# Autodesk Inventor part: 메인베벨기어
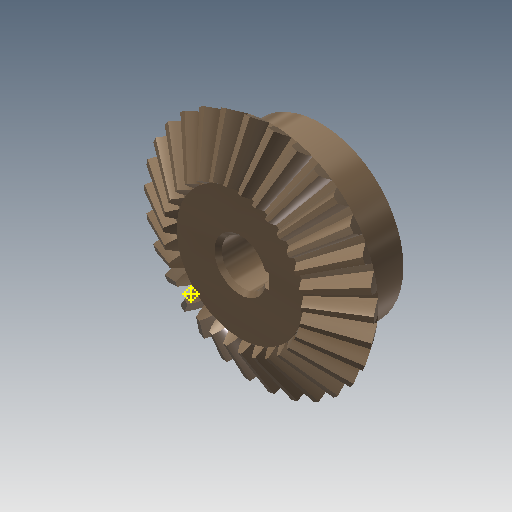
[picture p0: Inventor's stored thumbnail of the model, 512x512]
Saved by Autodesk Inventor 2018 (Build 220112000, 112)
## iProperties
Created: 2018-09
Part Number: 메인베벨기어
Material: 강철, 탄소
Document SubType Name: Modeling
Categories: <?xml version="1.0" encoding="UTF-16"?> <MemberInstance><Categories><FamilyTemplate><FamilyTemplateParameter ValueType="xs:double" Id="1" ObjectReferenceKey="da
Mass: 290.333 g
Surface Area: 107.709 cm^2
Volume: 36.8911 cm^3
Density: 7.87 g/cm^3
Appearance: 얼룩무늬
CustomPartVersion: 1
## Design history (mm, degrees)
node "맨 위 점"
node "메쉬 평면2"
sketch "톱니 본체 스케치"
  geometry: L1 (0, 0)-(28.669, -21.997); L2 (28.669, -21.997)-(31.109, -18.336); L3 (31.109, -18.336)-(0, 0); L4 (30, -20)-(0, 0); L5 (17.219, -13.212)-(18.685, -11.013); L6 (28.669, -21.997)-(17.219, -13.212); L7 (31.109, -18.336)-(18.685, -11.013); L8 (0, -39.387)-(0, 6.564) reference; L9 (0, -20)-(31.109, -20)
  constraints: 16 end point, 4 point on line, 3 perpendicular, 2 collinear, 1 horizontal alignment, 1 vertical alignment
  dimensions: "d0" = 60 diameter of L4.start L8 (= da_de); "d1" = 57.33744 diameter of L1.end L8 (= da_dfe); "d2" = 62.2188 diameter of L2.end L8 (= da_dae); "d3" = 14.4 distance between parallel lines of L2 L5 (= da_b); "d4" = 18.3359 vertical distance of L2.end L1.start (= da_ve)
revolve "톱니 본체" sketch "톱니 본체 스케치" stored, may be unused: angle "d5" = 90 deg
node "시작점"
node "톱니 평면"
sketch "시작 스케치"
  geometry: L1 (0, -23.505)-(0, 10.645) reference; L2 (-0.709, -2.928)-(0.709, -2.928); A1 r 19.188 centre (-19.457, -7.014) between (-0.709, -2.928) and (-3.232, 3.229); A2 r 19.188 centre (19.457, -7.014) between (3.232, 3.229) and (0.709, -2.928); A3 r 57.403 centre (0, -54.083) between (3.232, 3.229) and (-3.232, 3.229); 1 further point
  constraints: 6 point on circle, 3 centre point, 3 symmetric about line, 2 end point, 1 coincident, 1 perpendicular, 1 other
  dimensions: "d7" = 19.18795 radius of A1 (= fd_rr); "d8" = 19.45712 horizontal distance of point (0, -54.083) A1.centre (= fd_x); "d9" = 47.06905 vertical distance of point (0, -54.083) A1.centre (= fd_y); "d57" = 57.40327 radius of A3 (= 0.5 x fd_dva + 0.3 x da_he); "d58" = 51.15527 distance from line of A3.centre L2 (= 0.5 x fd_dva - 1.12 x da_he)
node "끝점"
  node "끝 평면"
sketch "3D 스케치 오른쪽"
  node "Helical Curve Right" dims "d65" = 229.90621 (computed from da_dm, da_delta, da_beta), "d66" = 31.5, "d67" = 60 (= da_de), "d68" = -9.82794 (= -da_delta), "d69" = 8.10972 (computed from fd_loft, da_delta)
node "끝 평면 오른쪽"
sketch "끝 스케치 오른쪽"
  geometry: L1 (0, -41.54)-(0, 13.178) reference; L2 (-0.422, -1.69)-(0.422, -1.69); A1 r 11.427 centre (-11.587, -4.123) between (-0.422, -1.69) and (-1.925, 1.977); A2 r 11.427 centre (11.587, -4.123) between (1.925, 1.977) and (0.422, -1.69); A3 r 34.184 centre (0, -32.153) between (1.925, 1.977) and (-1.925, 1.977); 1 further point
  constraints: 6 point on circle, 3 centre point, 3 symmetric about line, 2 end point, 1 coincident, 1 perpendicular, 1 other
  dimensions: "d70" = 11.58699 horizontal distance of A3.centre A1.centre (computed from fd_x, fd_ratio); "d71" = 28.03028 vertical distance of point (0, -32.153) A1.centre (computed from fd_y, fd_ratio); "d72" = 11.4267 radius of A1 (computed from fd_rr, fd_ratio); "d73" = 30.46369 distance from line of point (0, -32.153) L2 (computed from d58, fd_ratio); "d74" = 34.18446 radius of A3 (computed from d57, fd_ratio)
feature "로프트 오른쪽" sketch "끝 스케치 오른쪽" dims "d75" = 0, "d77" = 0, "d79" = 0, "d80" = 90 deg, "d85" = 20, "d92" = 90 deg, "d93" = 90 deg, "da_teethtype" = 0 [user parameter]
sketch "3D 스케치 왼쪽"
  node "Helical Curve Left" dims "d26" = 229.90621 (computed from da_dm, da_delta, da_beta), "d27" = 8.10972 (computed from fd_loft, da_delta), "d28" = 60 (= da_de), "d29" = -9.82794 (= -da_delta)
node "끝 평면 왼쪽"
sketch "끝 스케치 왼쪽" dims "d56" = 10.3728 (derived)
  geometry: L1 (0, -43.753)-(0, 15.405) reference; L2 (-0.422, -1.678)-(0.422, -1.678); A1 r 11.427 centre (-11.587, -4.111) between (-0.422, -1.678) and (-1.925, 1.988); A2 r 11.427 centre (11.587, -4.111) between (1.925, 1.988) and (0.422, -1.678); A3 r 34.184 centre (0, -32.142) between (1.925, 1.988) and (-1.925, 1.988); 2 further points; 1 other entity
  constraints: 6 point on circle, 3 centre point, 3 symmetric about line, 2 end point, 1 coincident, 2 other
  dimensions: "d30" = 11.4267 radius of A1 (computed from fd_rr, fd_ratio); "d31" = 11.58699 horizontal distance of point (0, -32.142) A1.centre (computed from fd_x, fd_ratio); "d32" = 28.03028 vertical distance of A1.centre point (0, -32.142) (computed from fd_y, fd_ratio); "d61" = 34.18446 radius of A3 (computed from d57, fd_ratio); "d62" = 30.46369 distance from line of point (0, -32.142) L2 (computed from d58, fd_ratio)
feature "로프트 왼쪽" sketch "끝 스케치 왼쪽" dims "d35" = 0, "d37" = 0, "d39" = 0, "d40" = 90 deg, "d84" = 10, "d90" = 90 deg, "d91" = 90 deg, "da_teethtype" = 0 [user parameter]
sketch "본체 스케치"
  geometry: L1 (0, -35.038)-(0, -19.531) reference; L2 (28.669, -21.997)-(17.219, -13.212) reference; L3 (17.219, -13.212)-(0, -13.212); L4 (28.669, -21.997)-(0, -21.997)
  constraints: 4 end point, 2 perpendicular, 2 point on line
revolve "본체 고정" sketch "본체 스케치" stored, may be unused: angle "d46" = 90 deg
feature "피치 지름" dims angle "d47" = 90 deg
sketch "스케치8"
  geometry: C1 r 22.5 at (0, 0); 1 further point
  constraints: 1 centre point, 1 coincident
  dimensions: "d94" = 45 diameter of C1
extrude "돌출1" join sketch "스케치8" distance "d95" = 13; taper "d96" = 0 deg
sketch "스케치9"
  geometry: 1 further point
hole "구멍1" sketch "스케치9" at (0, 0) diameter "d97" = 12; stored, may be unused: countersink angle "d101" = 90 deg, drill point angle "d103" = 118 deg; dims "d98" = 6, "d99" = 4, "d100" = 2, "d102" = 8
sketch "스케치10"
  geometry: L1 (5.657, 2)-(7.8, 2); L2 (7.8, 2)-(7.8, -2); L3 (7.8, -2)-(5.657, -2); A1 r 6 centre (0, 0) between (5.657, 2) and (5.657, -2) reference; 1 further point
  constraints: 6 end point, 2 parallel, 2 point on circle, 1 horizontal, 1 perpendicular
  dimensions: "d104" = 4 distance of L1.end L2.end; "d112" = 13.8 dimension on A1 L2
extrude "돌출2" cut sketch "스케치10" extent not by distance; stored distance "d106" = 10; taper "d107" = 0 deg
chamfer "모따기1" distance "d108" = 1; stored, may be unused: second distance "d109" = 2, angle "d110" = 45 deg
fillet "모깎기1" dims "d111" = 2
body "Solid1"
feature "로프트" dims "d17" = 0, "d18" = 90 deg, "d19" = 0, "d20" = 90 deg, "d89" = 0, "da_teethtype" = 0 [user parameter]
pattern_circular "원형 패턴" dims angle "d22" = 360 deg, "d88" = 0, "da_teethtype" = 0 [user parameter]
pattern_circular "원형 패턴 오른쪽" dims angle "d82" = 360 deg, "da_teethtype" = 0 [user parameter]
pattern_circular "원형 패턴 왼쪽" dims angle "d42" = 360 deg, "da_teethtype" = 0 [user parameter]
sketch "끝 스케치"
  geometry: L1 (0, -15.359)-(0, 6.983) reference; L2 (-0.422, -1.69)-(0.422, -1.69); A1 r 11.427 centre (-11.587, -4.123) between (-0.422, -1.69) and (-1.925, 1.977); A2 r 11.427 centre (11.587, -4.123) between (1.925, 1.977) and (0.422, -1.69); A3 r 34.184 centre (0, -32.153) between (1.925, 1.977) and (-1.925, 1.977); 1 further point
  constraints: 6 point on circle, 3 centre point, 3 symmetric about line, 2 end point, 1 coincident, 1 other
  dimensions: "d12" = 11.4267 radius of A1 (computed from fd_rr, fd_ratio); "d15" = 11.58699 horizontal distance of A1.centre point (0, -32.153) (computed from fd_x, fd_ratio); "d16" = 28.03028 vertical distance of A1.centre point (0, -32.153) (computed from fd_y, fd_ratio); "d59" = 34.18446 radius of A3 (computed from d57, fd_ratio); "d60" = 30.46369 distance from line of A3.centre L2 (computed from d58, fd_ratio)
sketch "Sketch6"
  geometry: L1 (30, -20)-(0, 0) reference; L2 (0, -37.8)-(0, 6.3) reference
body "Srf1"
other parameters: "da_b" = 14.4 [user parameter; used in 2 equation terms], "da_de" = 60 [user parameter; used in 4 equation terms], "da_dae" = 62.2188 [user parameter; used in 2 equation terms], "da_dfe" = 57.33744 [user parameter; used in 1 equation term], "da_le" = 36.05551 [user parameter; used in 1 equation term], "da_omega" = 90 deg [user parameter; used in 1 equation term], "da_beta" = 0 [user parameter; used in 2 equation terms], "da_delta" = 9.82794 [user parameter; used in 8 equation terms], "da_alpha" = 20 deg [user parameter; used in 2 equation terms], "da_he" = 4.4 [user parameter; used in 4 equation terms], "da_ve" = 18.3359 [user parameter; used in 1 equation term], "fd_dv" = 108.16654 (computed from da_de, da_delta) [user parameter; used in 1 equation term], "fd_dva" = 112.16654 (computed from da_dae, da_delta) [user parameter; used in 3 equation terms], "fd_dvb" = 101.6433 (computed from fd_dv, da_alpha) [user parameter; used in 2 equation terms], "da_zv" = 540.83269 [user parameter; used in 1 equation term], "fd_loft" = 14.62 (= da_b + 0.05 x da_he) [user parameter; used in 4 equation terms], "fd_ratio" = 5.95514 (computed from da_le, fd_loft) [user parameter; used in 15 equation terms], "fd_rr" = 19.18795 (computed from fd_dd, fd_dvb) [user parameter; used in 6 equation terms], "fd_angle" = 0.29367 (computed from da_zv) [user parameter; used in 4 equation terms], "fd_x1" = 1.58802 (computed from da_dvw, fd_angle) [user parameter; used in 1 equation term], "fd_y1" = 54.05995 (computed from da_dvw, fd_angle) [user parameter; used in 1 equation term], "fd_x2" = 17.8691 (computed from fd_rr, fd_angle2, fd_angle) [user parameter; used in 1 equation term], "fd_y2" = 6.9909 (computed from fd_rr, fd_angle2, fd_angle) [user parameter; used in 1 equation term], "fd_x" = 19.45712 (= fd_x1 + fd_x2) [user parameter; used in 4 equation terms], "fd_y" = 47.06905 (= fd_y1 - fd_y2) [user parameter; used in 4 equation terms], "fd_angle2" = 3.43555 (computed from fd_dvb, fd_dd, da_alpha) [user parameter; used in 2 equation terms], "fd_dd" = 108.64654 (= fd_dva - 0.8 x da_he) [user parameter; used in 2 equation terms], "da_dvw" = 108.16654 [user parameter; used in 2 equation terms], "d11" = 14.62 (= fd_loft), "da_dm" = 48.01848 [user parameter; used in 2 equation terms], "da_x" = 0 [user parameter], "da_m" = 2 [user parameter], "d48" = 0, "d49" = 0, "d50" = 90 deg (= da_omega), "d51" = 6 deg (computed from da_z), "d52" = 0, "d53" = 0, "d54" = 0
